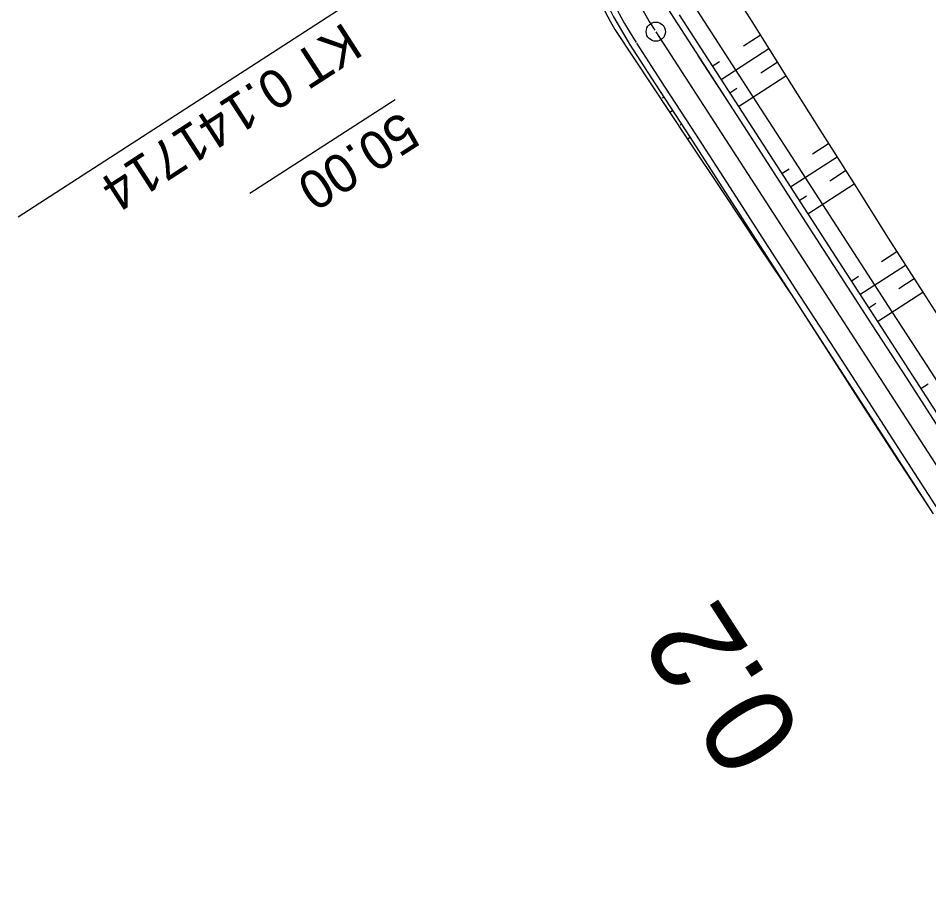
# Model space of a CAD drawing. Extents: x -481645 to -478728, y -1113199 to -1110710.
# Drawn here: x -481645.3 to -481574.2, y -1112752.1 to -1112684.6 of the extents above; entities that cross this region are included whole.
import ezdxf

# ---------------------------------------------------------------- set-up
doc = ezdxf.new("R2010")
doc.units = 0
for name, color, linetype in [('00_uprava', 7, 'Continuous'), ('Vrstva 41', 7, 'Continuous'), ('Vrstva 42', 7, 'Continuous'), ('Vrstva 43', 7, 'Continuous'), ('Vrstva 44', 7, 'Continuous'), ('Vrstva 45', 7, 'Continuous'), ('Vrstva 46', 7, 'Continuous'), ('Vrstva 47', 7, 'Continuous'), ('Vrstva 48', 7, 'Continuous'), ('Vrstva 49', 7, 'Continuous'), ('Vrstva 50', 7, 'Continuous'), ('Vrstva 51', 7, 'Continuous')]:
    doc.layers.add(name, color=color, linetype=linetype)

msp = doc.modelspace()

# ---------------------------------------------------------------- linework, layer by layer
at = {"layer": '00_uprava'}
for radius, start, end in [(32.25, 163.29936, 212.69414), (31.75, 163.29936, 212.69414), (30, 163.29936, 212.69414), (28.25, 163.29936, 212.69414), (32.65, 167.50485, 209.65193)]:
    msp.add_arc((-481570.357, -1112669.331), radius, start, end, dxfattribs=at)
at = {"layer": 'Vrstva 41'}
msp.add_line((-481595.531, -1112685.642), (-481552.546, -1112752.127), dxfattribs=at)
at = {"layer": 'Vrstva 42'}
for p, q in [((-481590.713, -1112680.624), (-481588.041, -1112684.85)), ((-481588.041, -1112684.85), (-481585.373, -1112689.08)), ((-481598.732, -1112685.484), (-481595.824, -1112689.882)), ((-481585.373, -1112689.08), (-481582.705, -1112693.308)), ((-481595.824, -1112689.882), (-481593.044, -1112694.039)), ((-481582.705, -1112693.308), (-481580.035, -1112697.536)), ((-481593.044, -1112694.039), (-481590.271, -1112698.2)), ((-481580.035, -1112697.536), (-481577.367, -1112701.765)), ((-481590.271, -1112698.2), (-481587.496, -1112702.36)), ((-481577.367, -1112701.765), (-481574.677, -1112705.98)), ((-481587.496, -1112702.36), (-481584.721, -1112706.52)), ((-481574.677, -1112705.98), (-481571.985, -1112710.194)), ((-481584.721, -1112706.52), (-481582.015, -1112710.724)), ((-481582.015, -1112710.724), (-481579.317, -1112714.934)), ((-481579.317, -1112714.934), (-481576.598, -1112719.13)), ((-481576.598, -1112719.13), (-481573.862, -1112723.316))]:
    msp.add_line(p, q, dxfattribs=at)
at = {"layer": 'Vrstva 43'}
for p, q in [((-481592.569, -1112683.588), (-481587.942, -1112690.74)), ((-481587.942, -1112690.74), (-481585.226, -1112694.939)), ((-481585.226, -1112694.939), (-481582.51, -1112699.137)), ((-481582.51, -1112699.137), (-481579.794, -1112703.335)), ((-481579.794, -1112703.335), (-481577.079, -1112707.533)), ((-481577.079, -1112707.533), (-481574.363, -1112711.731)), ((-481574.363, -1112711.731), (-481571.647, -1112715.929))]:
    msp.add_line(p, q, dxfattribs=at)
at = {"layer": 'Vrstva 44'}
for p, q in [((-481593.711, -1112684.32), (-481589.08, -1112691.476)), ((-481597.576, -1112686.624), (-481595.574, -1112689.72)), ((-481595.574, -1112689.72), (-481592.859, -1112693.919)), ((-481589.08, -1112691.476), (-481586.365, -1112695.675)), ((-481592.859, -1112693.919), (-481590.144, -1112698.118)), ((-481586.365, -1112695.675), (-481583.65, -1112699.874)), ((-481590.144, -1112698.118), (-481587.429, -1112702.317)), ((-481583.65, -1112699.874), (-481580.936, -1112704.073)), ((-481587.429, -1112702.317), (-481584.715, -1112706.516)), ((-481580.936, -1112704.073), (-481578.221, -1112708.271)), ((-481584.715, -1112706.516), (-481582, -1112710.715)), ((-481578.221, -1112708.271), (-481575.506, -1112712.47)), ((-481582, -1112710.715), (-481579.285, -1112714.914)), ((-481575.506, -1112712.47), (-481572.792, -1112716.669)), ((-481579.285, -1112714.914), (-481576.571, -1112719.112)), ((-481576.571, -1112719.112), (-481573.856, -1112723.311))]:
    msp.add_line(p, q, dxfattribs=at)
at = {"layer": 'Vrstva 45'}
for p, q in [((-481597.031, -1112686.545), (-481595.154, -1112689.449)), ((-481592.214, -1112687.549), (-481589.5, -1112691.748)), ((-481595.154, -1112689.449), (-481592.439, -1112693.648)), ((-481589.5, -1112691.748), (-481586.785, -1112695.946)), ((-481592.439, -1112693.648), (-481589.724, -1112697.847)), ((-481586.785, -1112695.946), (-481584.07, -1112700.145)), ((-481589.724, -1112697.847), (-481587.01, -1112702.046)), ((-481584.07, -1112700.145), (-481581.356, -1112704.344)), ((-481587.01, -1112702.046), (-481584.295, -1112706.244)), ((-481581.356, -1112704.344), (-481578.641, -1112708.543)), ((-481584.295, -1112706.244), (-481581.58, -1112710.443)), ((-481578.641, -1112708.543), (-481575.926, -1112712.742)), ((-481581.58, -1112710.443), (-481578.865, -1112714.642)), ((-481575.926, -1112712.742), (-481573.212, -1112716.941)), ((-481578.865, -1112714.642), (-481576.151, -1112718.841)), ((-481576.151, -1112718.841), (-481573.436, -1112723.04))]:
    msp.add_line(p, q, dxfattribs=at)
at = {"layer": 'Vrstva 46'}
for p, q in [((-481594.131, -1112684.59), (-481589.5, -1112691.748)), ((-481595.154, -1112689.449), (-481592.439, -1112693.648)), ((-481589.5, -1112691.748), (-481586.785, -1112695.946)), ((-481592.439, -1112693.648), (-481589.724, -1112697.847)), ((-481586.785, -1112695.946), (-481584.07, -1112700.145)), ((-481589.724, -1112697.847), (-481587.01, -1112702.046)), ((-481584.07, -1112700.145), (-481581.356, -1112704.344)), ((-481587.01, -1112702.046), (-481584.295, -1112706.244)), ((-481581.356, -1112704.344), (-481578.641, -1112708.543)), ((-481584.295, -1112706.244), (-481581.58, -1112710.443)), ((-481578.641, -1112708.543), (-481575.926, -1112712.742)), ((-481581.58, -1112710.443), (-481578.865, -1112714.642)), ((-481575.926, -1112712.742), (-481573.212, -1112716.941)), ((-481578.865, -1112714.642), (-481576.151, -1112718.841)), ((-481576.151, -1112718.841), (-481573.436, -1112723.04))]:
    msp.add_line(p, q, dxfattribs=at)
at = {"layer": 'Vrstva 47'}
msp.add_line((-481615.909, -1112690.96), (-481627.246, -1112698.29), dxfattribs=at)
at = {"layer": 'Vrstva 48'}
msp.add_line((-481620.407, -1112684.002), (-481645.349, -1112700.127), dxfattribs=at)
msp.add_circle((-481595.531, -1112685.642), 0.75, dxfattribs=at)
at = {"layer": 'Vrstva 50'}
for p, q in [((-481588.677, -1112686.75), (-481587.374, -1112685.908)), ((-481590.437, -1112689.377), (-481586.707, -1112686.965)), ((-481591.116, -1112688.327), (-481590.548, -1112687.96)), ((-481587.33, -1112688.856), (-481586.04, -1112688.022)), ((-481589.08, -1112691.476), (-481585.373, -1112689.08)), ((-481589.759, -1112690.426), (-481589.19, -1112690.058)), ((-481583.292, -1112695.176), (-481582.037, -1112694.365)), ((-481585.008, -1112697.774), (-481581.37, -1112695.422)), ((-481585.687, -1112696.725), (-481585.117, -1112696.356)), ((-481581.946, -1112697.283), (-481580.703, -1112696.479)), ((-481583.65, -1112699.874), (-481580.035, -1112697.536)), ((-481584.329, -1112698.824), (-481583.759, -1112698.456)), ((-481577.904, -1112703.602), (-481576.694, -1112702.819)), ((-481579.578, -1112706.172), (-481576.022, -1112703.873)), ((-481580.257, -1112705.122), (-481579.686, -1112704.753)), ((-481576.554, -1112705.704), (-481575.349, -1112704.926)), ((-481578.221, -1112708.271), (-481574.677, -1112705.98)), ((-481578.9, -1112707.222), (-481578.329, -1112706.852)), ((-481574.828, -1112713.52), (-481574.256, -1112713.15))]:
    msp.add_line(p, q, dxfattribs=at)
at = {"layer": 'Vrstva 51'}
for p, q in [((-481595.129, -1112690.921), (-481595.129, -1112690.921)), ((-481594.895, -1112690.77), (-481595.012, -1112690.846)), ((-481594.216, -1112691.82), (-481594.434, -1112691.961)), ((-481593.739, -1112693), (-481593.739, -1112693)), ((-481593.538, -1112692.87), (-481593.638, -1112692.935)), ((-481592.859, -1112693.919), (-481593.044, -1112694.039)), ((-481589.577, -1112699.24), (-481589.577, -1112699.24)), ((-481589.465, -1112699.168), (-481589.521, -1112699.204)), ((-481588.787, -1112700.218), (-481588.884, -1112700.28)), ((-481588.19, -1112701.32), (-481588.19, -1112701.32)), ((-481588.108, -1112701.267), (-481588.149, -1112701.294)), ((-481587.429, -1112702.317), (-481587.496, -1112702.36)), ((-481584.044, -1112707.571), (-481584.044, -1112707.571)), ((-481584.036, -1112707.566), (-481584.04, -1112707.568)), ((-481583.357, -1112708.615), (-481583.368, -1112708.622)), ((-481582.691, -1112709.673), (-481582.691, -1112709.673)), ((-481582.679, -1112709.665), (-481582.685, -1112709.669)), ((-481582, -1112710.715), (-481582.015, -1112710.724)), ((-481578.637, -1112715.983), (-481578.637, -1112715.983)), ((-481578.607, -1112715.963), (-481578.622, -1112715.973)), ((-481577.928, -1112717.013), (-481577.957, -1112717.032)), ((-481577.278, -1112718.081), (-481577.278, -1112718.081)), ((-481577.249, -1112718.063), (-481577.264, -1112718.072)), ((-481576.571, -1112719.112), (-481576.598, -1112719.13))]:
    msp.add_line(p, q, dxfattribs=at)

# ---------------------------------------------------------------- texts
at = {"layer": 'Vrstva 47'}
msp.add_text('50.00', height=2.999, rotation=212.88403, dxfattribs=at).set_placement((-481615.365, -1112691.799))
at = {"layer": 'Vrstva 48'}
msp.add_text('KT 0.141714', height=2.999, rotation=212.88403, dxfattribs=at).set_placement((-481619.864, -1112684.841))
at = {"layer": 'Vrstva 49'}
msp.add_text('0.2', height=7, rotation=122.8384, dxfattribs=at).set_placement((-481583.859, -1112740.546))

doc.saveas('drawing.dxf')
